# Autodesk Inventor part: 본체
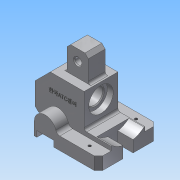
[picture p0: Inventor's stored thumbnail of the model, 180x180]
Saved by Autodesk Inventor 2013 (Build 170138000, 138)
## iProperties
Created: 2016-11
Part Number: 본체
Material: 알루미늄 6061
Document SubType Name: Modeling
Designer: Administrator
Density: 2.71 g/cm^3
Mass: 462.906 g
Surface Area: 317.29 cm^2
Volume: 170.814 cm^3
Author: Administrator
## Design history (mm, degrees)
sketch "스케치1"
  geometry: L1 (-34, -28)-(34, -28); L2 (34, -28)-(34, -20); L3 (20, 20)-(-20, 20); L4 (-38, 2)-(-38, -24); L5 (-20, 20)-(-38, 2); L6 (20, 20)-(20, -20); L7 (20, -20)-(34, -20); L8 (-34, -28)-(-38, -24); 6 further points
  constraints: 16 end point, 5 point on line, 3 parallel, 2 horizontal alignment, 2 midpoint, 2 perpendicular, 1 horizontal, 1 vertical alignment
  dimensions: "d2" = 48 distance of point (-38, 20) point (-38, -28); "d3" = 18 distance of L3.end point (-38, 20); "d4" = 18 distance of L4.start point (-38, 20) (= d3); "d5" = 72 distance of point (-38, -28) L1.end; "d6" = 58 distance between parallel lines of L6 L4; "d7" = 4 distance of L1.start point (-38, -28); "d8" = 4 distance of L4.end point (-38, -28) (= d7); "d10" = 8 distance of L1.end L2.end
extrude "돌출1" new body sketch "스케치1" stored distance "d11" = 40; taper "d12" = 0 deg
sketch "스케치2"
  geometry: L1 (-10, 20)-(15, 20); L2 (15, 20)-(15, 46); L3 (11, 50)-(-6, 50); L4 (-10, 46)-(-10, 20); L5 (-6, 50)-(-10, 46); L6 (11, 50)-(15, 46); L7 (20, 20)-(-20, 20) reference; 3 further points
  constraints: 12 end point, 5 point on line, 2 parallel, 1 horizontal, 1 perpendicular
  dimensions: "d13" = 25 distance of point (15, 50) point (-10, 50); "d15" = 4 distance of L3.end point (-10, 50); "d16" = 4 distance of L4.start point (-10, 50) (= d15); "d17" = 4 distance of L3.start point (15, 50) (= d15); "d18" = 4 distance of L2.end point (15, 50) (= d17); "d19" = 30 distance between parallel lines of L1 L3; "d20" = 5 distance from line of L2 L7.start
extrude "돌출2" join sketch "스케치2" stored distance "d21" = 20; taper "d22" = 0 deg
sketch "스케치3"
  geometry: L1 (0, -8)-(40, -8) reference; 2 further points
  constraints: 1 vertical alignment
  dimensions: "d23" = 30 distance from line of L1 point (20, 22)
hole "구멍1" sketch "스케치3" at (20, 22) diameter "d24" = 20; stored, may be unused: countersink angle "d28" = 90 deg, drill point angle "d30" = 118 deg; dims "d25" = 6, "d26" = 29, "d27" = 7, "d29" = 8
sketch "스케치4"
  geometry: L1 (-10, 46)-(-10, 20) reference; L2 (13, -8)-(13, 12) reference; L3 (13, 2)-(-45.414, 2); 2 further points
  constraints: 2 end point, 1 midpoint, 1 perpendicular
  dimensions: "d31" = 35 distance from line of L3 point (2.5, 37); "d33" = 12.5 distance from line of L1 point (2.5, 37)
hole "구멍2" sketch "스케치4" at (2.5, 37) diameter "d34" = 8; stored, may be unused: countersink angle "d38" = 90 deg, drill point angle "d40" = 118 deg; dims "d35" = 6, "d36" = 8, "d37" = 7, "d39" = 50
chamfer "모따기1" distance "d41" = 1; stored, may be unused: second distance "d42" = 2, angle "d43" = 45 deg
chamfer "모따기2" distance "d44" = 1; stored, may be unused: second distance "d45" = 2, angle "d46" = 45 deg
node "작업 평면1"
sketch "스케치5"
  geometry: L1 (-24, -25)-(-24, -40); L2 (-24, -40)-(-21, -40); L3 (-21, -40)-(-21, -33); L4 (-21, -33)-(-1, -33); L5 (-1, -33)-(-1, -40); L6 (-1, -40)-(34, -40); L7 (34, -40)-(34, -25); L8 (34, -25)-(6.292, -25); L9 (20, 20)-(-20, 20) reference; L10 (-38, 2)-(-38, -24) reference; A1 r 13 centre (-11, -25) between (1.488, -21.389) and (-24, -25); A2 r 5 centre (6.292, -20) between (1.488, -21.389) and (6.292, -25); 2 further points
  constraints: 16 end point, 5 point on circle, 4 parallel, 3 tangent, 2 centre point, 2 collinear, 2 perpendicular, 1 point on line, 1 vertical
  dimensions: "d48" = 26 diameter of A1; "d49" = 15 distance of L6.end L7.end; "d50" = 7 distance of L2.end L3.end; "d51" = 3 distance of L1.end L2.end; "d52" = 20 distance of L3.end L4.end; "d53" = 45 distance from line of L7 A1.centre; "d54" = 15 distance from line of L2 L1.start; "d55" = 5 radius of A2; "d56" = 60 distance between parallel lines of L6 L9; "d57" = 72 distance between parallel lines of L7 L10
extrude "돌출3" join sketch "스케치5" distance "d58" = 70; taper "d59" = 0 deg
sketch "스케치6"
  geometry: L1 (40, 0)-(0, 0) reference; L2 (-15, -20)-(55, -20) reference; L3 (40, -5)-(55, -5) reference; L4 (-15, -5)-(0, -5); L5 (0, -5)-(0, 0); L6 (0, 0)-(1.106, 0); L7 (38.894, 0)-(40, 0); L8 (40, 0)-(40, -5); L9 (40, -5)-(55, -5); L10 (55, -5)-(55, -20); L11 (55, -20)-(26, -20); L12 (26, -20)-(26, -6.373); L13 (-15, -5)-(-15, -20) reference; L14 (-15, -5)-(-15, -20); L15 (-15, -20)-(14, -20); L16 (14, -20)-(14, -6.373); C1 r 10 at (20, 22) reference; A1 r 29 centre (20, 22) between (26, -6.373) and (38.894, 0); A2 r 29 centre (20, 22) between (1.106, 0) and (14, -6.373); 1 further point
  constraints: 24 end point, 6 perpendicular, 4 point on circle, 4 point on line, 2 centre point, 2 collinear, 1 coincident
  dimensions: "d61" = 29 distance of L2.end L11.end; "d62" = 29 distance of L2.start L15.end; "d63" = 29 radius of A2; "d64" = 29 radius of A1
extrude "돌출4" join sketch "스케치6" distance "d65" = 18; taper "d66" = 0 deg
sketch "스케치7"
  geometry: L1 (20, -20)-(20, 20) reference; L2 (20, 20)-(-20, 20) reference; 2 further points
  constraints: 1 other
  dimensions: "d67" = 25 distance from line of L1 point (-5, 2); "d68" = 18 distance from line of point (-5, 2) L2
feature "엠보싱1" sketch "스케치7" dims "d69" = 0.5, "d70" = 0
fillet "모깎기1" dims "d71" = 3
chamfer "모따기3" distance "d72" = 5; stored, may be unused: second distance "d73" = 2, angle "d74" = 45 deg
sketch "스케치8"
  geometry: L1 (45.708, 15)-(45.708, 5) reference; L2 (27.708, 29)-(27.708, 41) reference; L3 (27.708, 35)-(-47.396, 35); L4 (45.708, 41)-(45.708, 65) reference; 3 further points
  constraints: 2 end point, 1 midpoint, 1 perpendicular
  dimensions: "d75" = 18 distance from line of L1 point (27.708, 7.5); "d76" = 27.5 distance from line of L3 point (27.708, 7.5); "d85" = 18 distance from line of L4 point (27.708, 62.5); "d86" = 27.5 distance from line of L3 point (27.708, 62.5)
hole "구멍3" sketch "스케치8" at (27.708, 7.5), (27.708, 62.5) diameter "d77" = 3.242; stored, may be unused: countersink angle "d81" = 90 deg, drill point angle "d83" = 118 deg; dims "d78" = 6, "d79" = 8, "d80" = 7, "d82" = 8
fillet "모깎기2" dims "d84" = 3
node "솔리드1"
other parameters: "d47" = 15, "d60" = 58
